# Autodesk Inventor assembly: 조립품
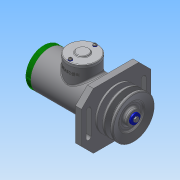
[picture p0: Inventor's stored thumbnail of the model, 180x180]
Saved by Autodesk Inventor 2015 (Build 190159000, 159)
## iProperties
Created: 2017-10
Part Number: 조립품
Document SubType Name: Assembly
Designer: Administrator
Author: Administrator
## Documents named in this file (20)
- C:\Users\Administrator\Desktop\471007v1010\조립품.iam
- C:\Users\Administrator\Desktop\471007v1010\본체.ipt
- C:\Users\Administrator\Desktop\471007v1010\축.ipt
- C:\Users\Administrator\Desktop\471007v1010\베어링 15 x 35 x 11.ipt
- C:\Users\Administrator\Desktop\471007v1010\부시1.ipt
- C:\Users\Administrator\Desktop\471007v1010\멈춤링 15 x 1.ipt
- C:\Users\Administrator\Desktop\471007v1010\멈춤링 35x1.6.ipt
- C:\Users\Administrator\Desktop\471007v1010\부시2.ipt
- C:\Users\Administrator\Desktop\471007v1010\와셔 10x21.ipt
- C:\Users\Administrator\Desktop\471007v1010\너트 M10.ipt
- C:\Users\Administrator\Desktop\471007v1010\사이드 커버.ipt
- 사이드 커버.ipt
- C:\Users\Administrator\Desktop\471007v1010\오일 실 15 25 7.ipt
- C:\Users\Administrator\Desktop\471007v1010\키 4 x 4 x 18.ipt
- C:\Users\Administrator\Desktop\471007v1010\V-벨트풀리.ipt
- C:\Users\Administrator\Desktop\471007v1010\와셔 4x16.ipt
- C:\Users\Administrator\Desktop\471007v1010\볼트 M4 x 10.ipt
- C:\Users\Administrator\Desktop\471007v1010\탑 커버.ipt
- C:\Users\Administrator\Desktop\471007v1010\와셔 3x6.ipt
- C:\Users\Administrator\Desktop\471007v1010\십자볼트 M3 x 10.ipt
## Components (2 placed, 2 different names)
1. V-벨트풀리:1
2. ISO 4017 M4 x 10:1 — 각도:4
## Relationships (1: Angle 1)
- 각도:4 [Angle]: ISO 4017 M4 x 10:1
